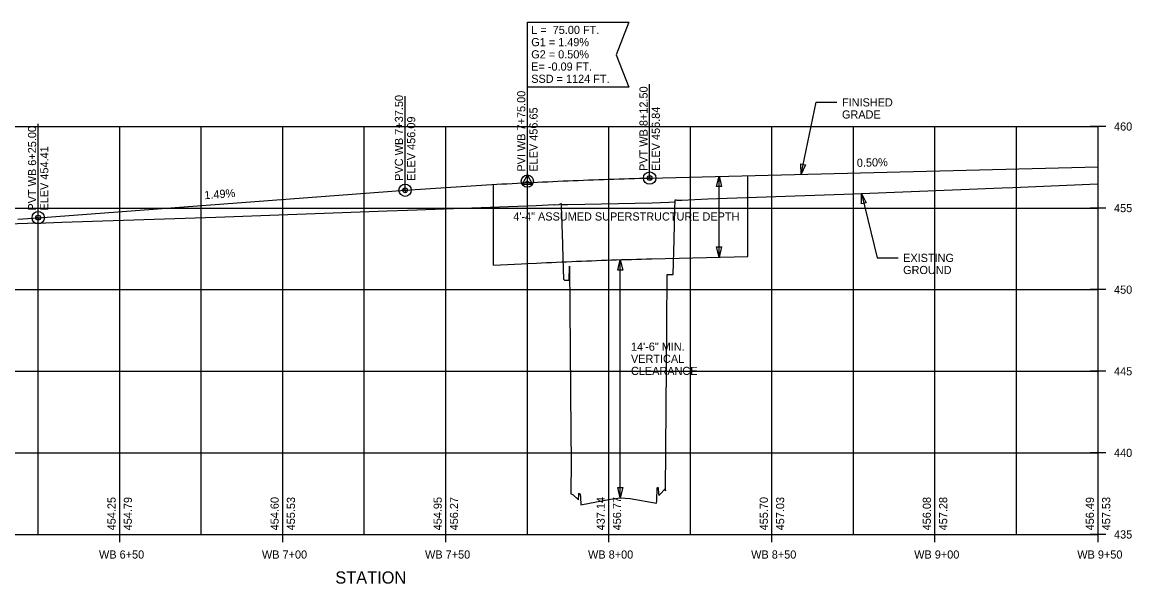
# Model space of a CAD drawing. Extents: x -1473 to -874, y -3319 to -2918.
# Drawn here: x -1215.7 to -875.5, y -3090.3 to -2918.2 of the extents above; entities that cross this region are included whole.
import ezdxf

# ---------------------------------------------------------------- set-up
doc = ezdxf.new("R2010")
doc.units = 0
for name, color, linetype in [('AC_P', 7, 'Continuous'), ('O_Details_Dimensions_Notes_P', 7, 'Continuous'), ('XANNOT_P_T', 7, 'Continuous'), ('XAX_P', 7, 'Continuous'), ('XAXTIC_P', 7, 'Continuous'), ('XAXTXT_P_T', 7, 'Continuous'), ('XSAFG1_P_T', 7, 'Continuous'), ('XSAOG1_C', 7, 'Continuous'), ('XSLFG1_P', 7, 'Continuous'), ('XSLOG1', 7, 'Continuous')]:
    doc.layers.add(name, color=color, linetype=linetype)

msp = doc.modelspace()

# ---------------------------------------------------------------- linework, layer by layer
at = {"layer": 'AC_P'}
for p, q in [((-993.21, -2990), (-993.21, -2965.24)), ((-1071.26, -2992.72), (-1071.26, -2967.95)), ((-1022.72, -2990.73), (-993.21, -2990))]:
    msp.add_line(p, q, dxfattribs=at)
msp.add_lwpolyline([(-1071.26, -2992.72), (-1062.68, -2992.27), (-1061.15, -2992.19), (-1058.06, -2992.04), (-1056.53, -2991.96), (-1054.99, -2991.89), (-1053.46, -2991.82), (-1051.92, -2991.75), (-1050.38, -2991.68), (-1048.85, -2991.62), (-1047.31, -2991.55), (-1045.77, -2991.49), (-1044.24, -2991.43), (-1042.7, -2991.37), (-1041.16, -2991.31), (-1039.62, -2991.25), (-1038.09, -2991.2), (-1036.55, -2991.14), (-1035.01, -2991.09), (-1033.48, -2991.04), (-1031.94, -2990.99), (-1030.4, -2990.95), (-1028.87, -2990.9), (-1027.33, -2990.86), (-1025.79, -2990.81), (-1024.26, -2990.77), (-1022.71, -2990.73)], dxfattribs=at)
at = {"layer": 'O_Details_Dimensions_Notes_P'}
for p, q in [((-1002.05, -2990.22), (-1002.05, -2965.46)), ((-1032.34, -3063.95), (-1032.34, -2991.09))]:
    msp.add_line(p, q, dxfattribs=at)
for points in [[(-1002.8, -2968.58), (-1002.05, -2965.46), (-1001.3, -2968.58)], [(-1001.3, -2987.09), (-1002.05, -2990.22), (-1002.8, -2987.09)], [(-1033.09, -2994.22), (-1032.34, -2991.09), (-1031.59, -2994.22)], [(-1031.59, -3060.83), (-1032.34, -3063.95), (-1033.09, -3060.83)]]:
    msp.add_lwpolyline(points, close=True, dxfattribs=at)
at = {"layer": 'XANNOT_P_T'}
for p, q in [((-1060.84, -2966.93), (-1060.84, -2938.13)), ((-1023.34, -2965.99), (-1023.34, -2937.19)), ((-1098.34, -2969.73), (-1098.34, -2940.93)), ((-1210.84, -2978.13), (-1210.84, -2949.33)), ((-1060.84, -2966.93), (-1062.47, -2967.87)), ((-1060.84, -2966.93), (-1060.84, -2965.04)), ((-1060.83, -2966.93), (-1059.21, -2967.87)), ((-1023.33, -2965.99), (-1024.08, -2965.99)), ((-1023.33, -2965.99), (-1023.33, -2965.25)), ((-1023.33, -2965.99), (-1023.33, -2966.74)), ((-1023.33, -2965.99), (-1022.59, -2965.99)), ((-1098.33, -2969.73), (-1099.08, -2969.73)), ((-1098.33, -2969.73), (-1098.33, -2968.98)), ((-1098.33, -2969.73), (-1098.33, -2970.47)), ((-1098.18, -2969.73), (-1097.59, -2969.73)), ((-1210.83, -2978.13), (-1211.58, -2978.13)), ((-1210.83, -2978.13), (-1210.83, -2977.38)), ((-1210.83, -2978.13), (-1210.83, -2978.87)), ((-1210.83, -2978.13), (-1210.09, -2978.13))]:
    msp.add_line(p, q, dxfattribs=at)
for points in [[(-1060.84, -2918.24), (-1029.76, -2918.24), (-1033.58, -2928.19), (-1029.76, -2938.13), (-1060.84, -2938.13)], [(-1060.84, -2965.04), (-1062.47, -2967.87), (-1059.21, -2967.87)]]:
    msp.add_lwpolyline(points, close=True, dxfattribs=at)
for centre, radius in [((-1060.84, -2966.93), 1.88), ((-1023.33, -2965.99), 1.89), ((-1023.33, -2965.99), 0.744), ((-1023.33, -2965.99), 0.154), ((-1098.33, -2969.73), 1.89), ((-1098.33, -2969.73), 0.744), ((-1098.33, -2969.73), 0.154), ((-1210.83, -2978.13), 1.89), ((-1210.83, -2978.13), 0.744), ((-1210.83, -2978.13), 0.154)]:
    msp.add_circle(centre, radius, dxfattribs=at)
at = {"layer": 'XAX_P'}
for p, q in [((-1335.84, -2950.19), (-885.84, -2950.19)), ((-1335.84, -2950.19), (-885.84, -2950.19)), ((-1210.84, -3075.19), (-1210.84, -2950.19)), ((-1185.84, -3075.19), (-1185.84, -2950.19)), ((-1160.84, -3075.19), (-1160.84, -2950.19)), ((-1135.84, -3075.19), (-1135.84, -2950.19)), ((-1110.84, -3075.19), (-1110.84, -2950.19)), ((-1085.84, -3075.19), (-1085.84, -2950.19)), ((-1060.84, -3075.19), (-1060.84, -2950.19)), ((-1035.84, -3075.19), (-1035.84, -2950.19)), ((-1010.84, -3075.19), (-1010.84, -2950.19)), ((-985.84, -3075.19), (-985.84, -2950.19)), ((-960.84, -3075.19), (-960.84, -2950.19)), ((-935.84, -3075.19), (-935.84, -2950.19)), ((-910.84, -3075.19), (-910.84, -2950.19)), ((-885.84, -3075.19), (-885.84, -2950.19)), ((-1335.84, -2975.19), (-885.84, -2975.19)), ((-1335.84, -3000.19), (-885.84, -3000.19)), ((-1335.84, -3025.19), (-885.84, -3025.19)), ((-1335.84, -3050.19), (-885.84, -3050.19)), ((-1335.84, -3075.19), (-885.84, -3075.19))]:
    msp.add_line(p, q, dxfattribs=at)
at = {"layer": 'XAXTIC_P'}
for p, q in [((-883.44, -2950.19), (-888.24, -2950.19)), ((-883.44, -2950.19), (-888.24, -2950.19)), ((-883.44, -2975.19), (-888.24, -2975.19)), ((-883.44, -3000.19), (-888.24, -3000.19)), ((-883.44, -3025.19), (-888.24, -3025.19)), ((-883.44, -3050.19), (-888.24, -3050.19)), ((-1210.84, -3075.19), (-1210.84, -3073.99)), ((-1185.84, -3077.59), (-1185.84, -3072.79)), ((-1160.84, -3075.19), (-1160.84, -3073.99)), ((-1135.84, -3077.59), (-1135.84, -3072.79)), ((-1110.84, -3075.19), (-1110.84, -3073.99)), ((-1085.84, -3077.59), (-1085.84, -3072.79)), ((-1060.84, -3075.19), (-1060.84, -3073.99)), ((-1035.84, -3077.59), (-1035.84, -3072.79)), ((-1010.84, -3075.19), (-1010.84, -3073.99)), ((-985.84, -3077.59), (-985.84, -3072.79)), ((-960.84, -3075.19), (-960.84, -3073.99)), ((-935.84, -3077.59), (-935.84, -3072.79)), ((-910.84, -3075.19), (-910.84, -3073.99)), ((-883.44, -3075.19), (-888.24, -3075.19)), ((-885.84, -3077.59), (-885.84, -3072.79))]:
    msp.add_line(p, q, dxfattribs=at)
at = {"layer": 'XSAFG1_P_T'}
for p, q in [((-976.92, -2964.83), (-972.26, -2942.77)), ((-972.26, -2942.77), (-965.92, -2942.77))]:
    msp.add_line(p, q, dxfattribs=at)
msp.add_lwpolyline([(-975.54, -2961.93), (-976.92, -2964.83), (-977.01, -2961.62)], close=True, dxfattribs=at)
at = {"layer": 'XSAOG1_C'}
for p, q in [((-958.38, -2970.69), (-953.52, -2990.42)), ((-953.52, -2990.42), (-947.18, -2990.42))]:
    msp.add_line(p, q, dxfattribs=at)
msp.add_lwpolyline([(-958.36, -2973.9), (-958.38, -2970.69), (-956.9, -2973.54)], close=True, dxfattribs=at)
at = {"layer": 'XSLFG1_P'}
for p, q in [((-1023.34, -2965.99), (-885.84, -2962.55)), ((-1210.84, -2978.13), (-1098.34, -2969.73))]:
    msp.add_line(p, q, dxfattribs=at)
for points in [[(-1098.34, -2969.73), (-1096.77, -2969.61), (-1095.21, -2969.5), (-1093.65, -2969.39), (-1092.09, -2969.27), (-1090.52, -2969.16), (-1088.96, -2969.06), (-1087.4, -2968.95), (-1085.84, -2968.85), (-1084.27, -2968.74), (-1082.71, -2968.64), (-1081.15, -2968.54), (-1079.59, -2968.44), (-1078.02, -2968.35), (-1076.46, -2968.25), (-1074.9, -2968.16), (-1073.34, -2968.07), (-1071.77, -2967.98), (-1070.21, -2967.89), (-1068.65, -2967.8), (-1067.09, -2967.72), (-1065.52, -2967.63), (-1063.96, -2967.55), (-1062.4, -2967.47), (-1059.27, -2967.32), (-1057.71, -2967.24), (-1056.15, -2967.17), (-1054.59, -2967.1), (-1053.02, -2967.02), (-1051.46, -2966.96), (-1049.9, -2966.89), (-1048.34, -2966.82), (-1046.77, -2966.76), (-1045.21, -2966.7), (-1043.65, -2966.64), (-1042.09, -2966.58), (-1040.52, -2966.52), (-1038.96, -2966.46), (-1037.4, -2966.41), (-1035.84, -2966.36), (-1034.27, -2966.3), (-1032.71, -2966.25), (-1031.15, -2966.21), (-1029.59, -2966.16), (-1028.02, -2966.12), (-1026.46, -2966.07), (-1024.9, -2966.03), (-1023.34, -2965.99)], [(-1217.09, -2978.58), (-1215.52, -2978.47), (-1213.96, -2978.36), (-1212.4, -2978.24), (-1210.84, -2978.13)]]:
    msp.add_lwpolyline(points, dxfattribs=at)
at = {"layer": 'XSLOG1'}
for points in [[(-1235.98, -2980.57), (-1214.14, -2979.84), (-1208.45, -2979.67), (-1203.59, -2979.53), (-1156.4, -2978), (-1156.36, -2978), (-1103.85, -2975.99), (-1097.59, -2975.86), (-1058.13, -2974.37), (-1054.47, -2974.17), (-1052.76, -2974.1), (-1052.64, -2974.09), (-1052.61, -2974.15), (-1051.05, -2974.09), (-1050.46, -2973.79), (-1050.46, -2973.79), (-1050.46, -2974.06), (-1050.44, -2974.5), (-1050.06, -2986.3), (-1050.06, -2986.36), (-1049.91, -2990.53), (-1049.71, -2996.97), (-1049.42, -2997.32), (-1047.98, -2997.31), (-1047.88, -2992.96), (-1047.49, -3043.88), (-1047.4, -3052.69), (-1047.49, -3062.65), (-1047.46, -3062.85), (-1047.36, -3062.73), (-1046.74, -3063.07), (-1045.19, -3064.55), (-1045.05, -3062.93), (-1045.03, -3062.55), (-1044.76, -3062.78), (-1044.64, -3062.85), (-1044.59, -3063.77), (-1044.48, -3066.08), (-1035.31, -3064.41), (-1032.34, -3063.95), (-1029.35, -3064.14), (-1021.22, -3065.62), (-1021.16, -3064.74), (-1021.05, -3060.86), (-1020.82, -3060.77), (-1020.72, -3060.81), (-1020.58, -3062.8), (-1020.55, -3063.29), (-1020.11, -3062.81), (-1018.65, -3061.27), (-1018.54, -3061.49), (-1018.48, -3061.87), (-1018.11, -3011.09), (-1017.97, -2995.52), (-1017.67, -2995.52), (-1016.16, -2995.52), (-1015.81, -2984.91), (-1015.57, -2975.21), (-1015.51, -2973.03), (-1015.51, -2972.68), (-1015.31, -2972.67), (-1015.02, -2972.79), (-1013.72, -2972.74), (-1013.71, -2972.74), (-1013.44, -2972.73), (-1005.52, -2972.36), (-963.77, -2970.9), (-958.38, -2970.69), (-915.22, -2969), (-912.02, -2968.87), (-885.98, -2967.76), (-885.98, -2967.76), (-885.84, -2967.76)], [(-1050.46, -2974.12), (-1048.98, -2974.1), (-1048.41, -2974.07), (-1022.61, -2973.58), (-1017.48, -2973.37), (-1015.78, -2973.31), (-1015.51, -2973.3)]]:
    msp.add_lwpolyline(points, dxfattribs=at)

# ---------------------------------------------------------------- texts
at = {"layer": 'O_Details_Dimensions_Notes_P'}
for s, p in [('4\'-4" ASSUMED SUPERSTRUCTURE DEPTH', (-1065.14, -2979.01)), ('14\'-6" MIN.', (-1029.06, -3018.9)), ('VERTICAL', (-1029.06, -3022.61)), ('CLEARANCE', (-1029.06, -3026.33))]:
    msp.add_text(s, height=2.496, dxfattribs=at).set_placement(p)
at = {"layer": 'XANNOT_P_T'}
for s, p in [('L =  75.00 FT.', (-1059.65, -2921.85)), ('G1 = 1.49%', (-1059.65, -2925.59)), ('G2 = 0.50%', (-1059.65, -2929.33)), ('E= -0.09 FT.', (-1059.65, -2933.08)), ('SSD = 1124 FT.', (-1059.65, -2936.82))]:
    msp.add_text(s, height=2.496, dxfattribs=at).set_placement(p)
for s, height, rotation, p in [('PVI WB 7+75.00', 2.5008, 90, (-1061.46, -2964.05)), ('PVT WB 8+12.50', 2.5008, 90, (-1023.96, -2963.83)), ('PVC WB 7+37.50', 2.5008, 90, (-1098.96, -2966.85)), ('ELEV 456.65', 2.5008, 90, (-1057.71, -2964.05)), ('ELEV 456.84 ', 2.5008, 90, (-1020.21, -2963.83)), ('ELEV 456.09 ', 2.5008, 90, (-1095.21, -2966.85)), ('PVT WB 6+25.00', 2.5008, 90, (-1211.46, -2975.97)), ('ELEV 454.41 ', 2.5008, 90, (-1207.71, -2975.97)), ('0.50% ', 2.501, 1.4321, (-959.78, -2962.58)), ('1.49% ', 2.501, 4.269, (-1159.8, -2972.49)), ('454.25', 2.501, 90, (-1187.09, -3073.94)), ('454.79', 2.501, 90, (-1182.09, -3073.94)), ('454.60', 2.501, 90, (-1137.09, -3073.94)), ('455.53', 2.501, 90, (-1132.09, -3073.94)), ('454.95', 2.501, 90, (-1087.09, -3073.94)), ('456.27', 2.501, 90, (-1082.09, -3073.94)), ('437.14', 2.501, 90, (-1037.09, -3073.94)), ('456.77', 2.501, 90, (-1032.09, -3073.94)), ('455.70', 2.501, 90, (-987.09, -3073.94)), ('457.03', 2.501, 90, (-982.09, -3073.94)), ('456.08', 2.501, 90, (-937.09, -3073.94)), ('457.28', 2.501, 90, (-932.09, -3073.94)), ('456.49', 2.501, 90, (-887.09, -3073.94)), ('457.53', 2.501, 90, (-882.09, -3073.94))]:
    msp.add_text(s, height=height, rotation=rotation, dxfattribs=at).set_placement(p)
at = {"layer": 'XAXTXT_P_T'}
for s, height, p in [('460', 2.501, (-880.94, -2951.44)), ('460', 2.501, (-880.94, -2951.44)), ('455', 2.501, (-880.94, -2976.44)), ('450', 2.501, (-880.94, -3001.44)), ('445', 2.501, (-880.94, -3026.44)), ('440', 2.501, (-880.94, -3051.44)), ('435', 2.501, (-880.94, -3076.44)), ('WB 6+50', 2.501, (-1192.19, -3082.59)), ('WB 7+00', 2.501, (-1142.22, -3082.59)), ('WB 7+50', 2.501, (-1092.21, -3082.59)), ('WB 8+00', 2.501, (-1042.22, -3082.59)), ('WB 8+50', 2.501, (-992.21, -3082.59)), ('WB 9+00', 2.501, (-942.22, -3082.59)), ('WB 9+50', 2.501, (-892.21, -3082.59)), ('STATION', 3.754, (-1119.73, -3090.26))]:
    msp.add_text(s, height=height, dxfattribs=at).set_placement(p)
at = {"layer": 'XSAFG1_P_T'}
for s, p in [('FINISHED ', (-964.36, -2944.05)), ('GRADE', (-964.36, -2947.76))]:
    msp.add_text(s, height=2.496, dxfattribs=at).set_placement(p)
at = {"layer": 'XSAOG1_C'}
for s, p in [('EXISTING ', (-945.61, -2991.7)), ('GROUND', (-945.61, -2995.41))]:
    msp.add_text(s, height=2.496, dxfattribs=at).set_placement(p)

doc.saveas('drawing.dxf')
